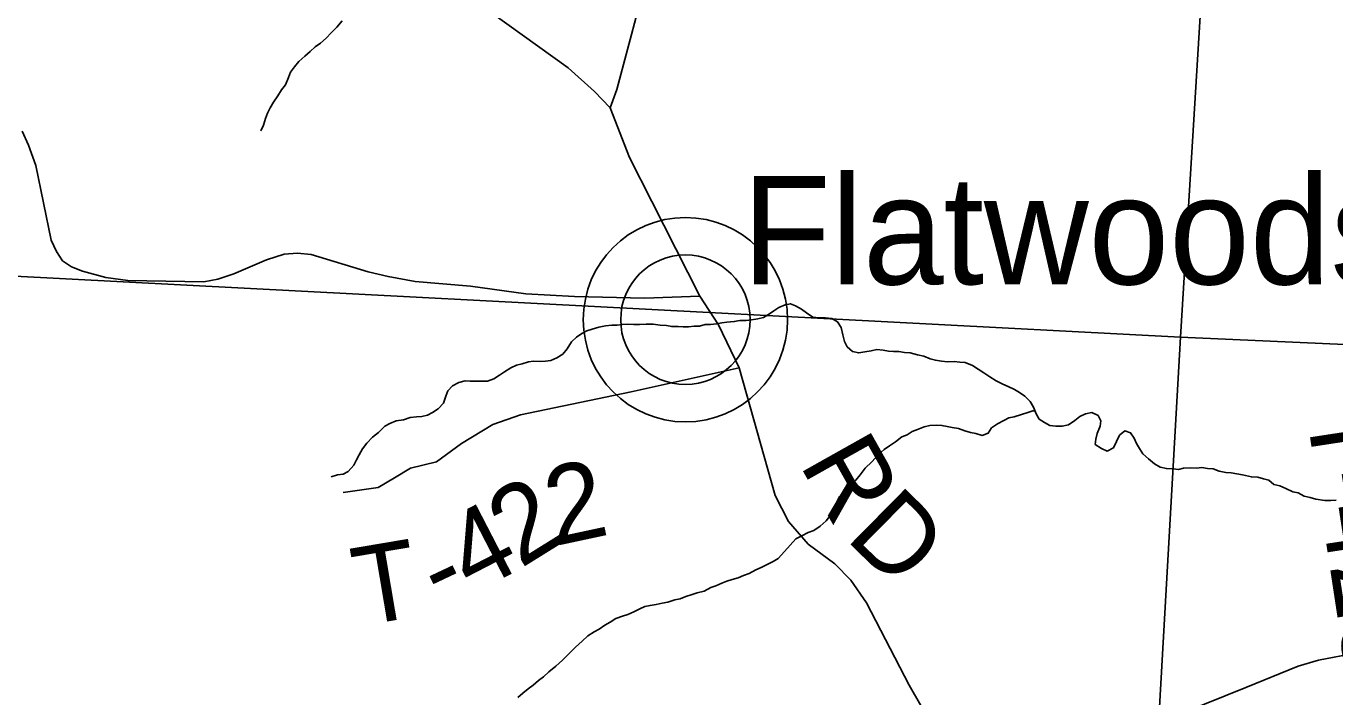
# Model space of a CAD drawing. Extents: x -20.2 to 34, y 0 to 22.
# Drawn here: x 7.079 to 8.033, y 16.636 to 17.124 of the extents above; entities that cross this region are included whole.
import ezdxf

# ---------------------------------------------------------------- set-up
doc = ezdxf.new("R2010")
doc.units = 0
for name, color, linetype in [('Default', 7, 'Continuous'), ('GM_X_County_Road', 7, 'Continuous'), ('GM_X_County_Road_Text', 7, 'Continuous'), ('GM_X_Minor_River', 7, 'Continuous'), ('GM_X_Section', 7, 'Continuous'), ('GM_X_Township_Road', 7, 'Continuous'), ('GM_X_Township_Road_Text', 7, 'Continuous'), ('GM_X_Unincorporated', 7, 'Continuous'), ('GM_X_Unincorporated_Location', 7, 'Continuous'), ('GM_X_Unincorporated_Text', 7, 'Continuous')]:
    doc.layers.add(name, color=color, linetype=linetype)

msp = doc.modelspace()

# ---------------------------------------------------------------- linework, layer by layer
at = {"layer": 'Default'}
for points in [[(8.9, 16.85373), (8.9, 17.84514), (7.98194, 17.90766), (7.92004, 16.89751)], [(8.9, 15.82114), (8.9, 16.85373), (7.92004, 16.89751), (7.86237, 15.87982)]]:
    msp.add_lwpolyline(points, close=True, dxfattribs=at)
at = {"layer": 'GM_X_County_Road'}
for points in [[(7.5047, 17.06445), (7.50945, 17.07768), (7.53298, 17.1663)], [(7.40706, 17.1417), (7.47411, 17.09347), (7.49333, 17.07622), (7.5047, 17.06445), (7.51882, 17.02837), (7.5349, 16.99622), (7.56986, 16.92742), (7.58352, 16.90642), (7.59849, 16.87511), (7.62484, 16.78214), (7.6345, 16.76328), (7.64898, 16.74682), (7.66821, 16.73251), (7.67999, 16.72053), (7.69136, 16.70406), (7.72235, 16.64406), (7.74979, 16.59622)], [(7.90619, 16.61759), (7.96766, 16.64232), (8.00584, 16.65793), (8.02072, 16.66225), (8.04858, 16.66753)]]:
    msp.add_lwpolyline(points, dxfattribs=at)
at = {"layer": 'GM_X_Minor_River'}
for points in [[(7.25027, 17.04764), (7.25212, 17.05185), (7.25358, 17.0568), (7.25506, 17.06062), (7.25691, 17.06444), (7.25952, 17.06865), (7.2625, 17.07325), (7.26511, 17.07746), (7.2681, 17.08129), (7.27032, 17.08664), (7.27179, 17.09046), (7.27478, 17.09429), (7.27777, 17.09813), (7.28228, 17.10199), (7.28604, 17.10545), (7.28979, 17.10892), (7.29356, 17.11163), (7.29769, 17.1151), (7.30144, 17.11894), (7.30557, 17.12317), (7.30931, 17.12778)], [(7.30143, 16.79569), (7.30596, 16.79727), (7.31014, 16.7977), (7.31391, 16.79965), (7.31803, 16.80426), (7.31988, 16.80808), (7.32174, 16.8119), (7.32434, 16.81611), (7.32733, 16.82033), (7.33146, 16.82456), (7.33597, 16.82803), (7.34047, 16.83264), (7.34425, 16.83459), (7.34878, 16.83655), (7.35408, 16.83738), (7.359, 16.83896), (7.36355, 16.83939), (7.36734, 16.83982), (7.37151, 16.84063), (7.37528, 16.84258), (7.37942, 16.84529), (7.38317, 16.84952), (7.38501, 16.85448), (7.38648, 16.85829), (7.38985, 16.86213), (7.39438, 16.86447), (7.39892, 16.86567), (7.40272, 16.86533), (7.40652, 16.86538), (7.41032, 16.86543), (7.41525, 16.86549), (7.41978, 16.86707), (7.42393, 16.86978), (7.4277, 16.87211), (7.43221, 16.8752), (7.43637, 16.87715), (7.44053, 16.87796), (7.44507, 16.87954), (7.44886, 16.87997), (7.4538, 16.87965), (7.45759, 16.88008), (7.46138, 16.8805), (7.46591, 16.88246), (7.47006, 16.88517), (7.47343, 16.88901), (7.47641, 16.89399), (7.48016, 16.89745), (7.48393, 16.90016), (7.4877, 16.90211), (7.49148, 16.90329), (7.4964, 16.90487), (7.50132, 16.9057), (7.50587, 16.90613), (7.50967, 16.90618), (7.51346, 16.90661), (7.51763, 16.90704), (7.52181, 16.90671), (7.52599, 16.90677), (7.53092, 16.90683), (7.53585, 16.90689), (7.54117, 16.9062), (7.54573, 16.90587), (7.54954, 16.90516), (7.55409, 16.90522), (7.55789, 16.90489), (7.56169, 16.90494), (7.56586, 16.90537), (7.56965, 16.90542), (7.57382, 16.90661), (7.57761, 16.90666), (7.58216, 16.90709), (7.58595, 16.9079), (7.58974, 16.90833), (7.59505, 16.90877), (7.59921, 16.90959), (7.60377, 16.90964), (7.60756, 16.91007), (7.6121, 16.91089), (7.61627, 16.9117), (7.62004, 16.91403), (7.6238, 16.91673), (7.62757, 16.91906), (7.6321, 16.92101), (7.63589, 16.92182), (7.6397, 16.92035), (7.64391, 16.91775), (7.64774, 16.91513), (7.65233, 16.91215), (7.65689, 16.91145), (7.66144, 16.91151), (7.666, 16.91118), (7.67021, 16.90858), (7.67291, 16.90443), (7.67411, 16.89913), (7.67531, 16.89421), (7.67725, 16.89044), (7.68109, 16.88707), (7.68566, 16.88598), (7.6902, 16.8868), (7.69475, 16.88762), (7.69891, 16.88843)], [(7.69891, 16.88843), (7.70347, 16.88811), (7.70728, 16.88739), (7.71108, 16.88706), (7.71487, 16.88711), (7.71906, 16.8864), (7.72323, 16.88608), (7.72857, 16.88462), (7.73313, 16.88354), (7.73771, 16.8817), (7.74152, 16.88061), (7.74608, 16.87991), (7.75064, 16.87958), (7.7552, 16.87964), (7.75937, 16.87932), (7.76317, 16.87898), (7.76851, 16.87677), (7.77272, 16.87417), (7.77693, 16.87156), (7.78114, 16.86857), (7.78573, 16.86559), (7.79069, 16.86337), (7.7945, 16.86152), (7.79909, 16.8593), (7.80291, 16.85707), (7.80673, 16.85446), (7.81057, 16.85071), (7.8129, 16.84656), (7.81485, 16.84165), (7.81718, 16.83788), (7.821, 16.83527), (7.82483, 16.83304), (7.82939, 16.83271), (7.83394, 16.83277), (7.83848, 16.83359), (7.843, 16.83668), (7.84676, 16.83977), (7.85092, 16.84172), (7.85546, 16.84254), (7.86004, 16.84032), (7.86198, 16.83654), (7.86165, 16.83274), (7.85943, 16.82739), (7.85834, 16.8232), (7.85801, 16.8194), (7.8626, 16.81642), (7.86679, 16.81457), (7.87132, 16.81691), (7.87355, 16.8215), (7.87577, 16.82608), (7.87953, 16.82917), (7.88372, 16.8277), (7.88642, 16.82394), (7.88799, 16.82016), (7.89031, 16.81639), (7.89263, 16.81262), (7.89685, 16.80887), (7.90107, 16.80513), (7.90527, 16.8029), (7.90984, 16.80182), (7.91478, 16.8015), (7.91857, 16.80117), (7.92236, 16.80198), (7.92729, 16.80242), (7.93185, 16.8021), (7.93564, 16.80252), (7.93982, 16.80182), (7.944, 16.80149), (7.9482, 16.80002), (7.95314, 16.79895), (7.95694, 16.79861), (7.96113, 16.79791), (7.96531, 16.7972), (7.97178, 16.79576), (7.97634, 16.79544), (7.98053, 16.79435), (7.98434, 16.79326), (7.98817, 16.79027), (7.99236, 16.78918), (7.99693, 16.78734), (8.0019, 16.78475), (8.0057, 16.78403), (8.01028, 16.78181), (8.01447, 16.78072), (8.01866, 16.77964), (8.02512, 16.77858), (8.02968, 16.77864), (8.03347, 16.77868)], [(7.60176, 16.72388), (7.60592, 16.72545), (7.61082, 16.72817), (7.6146, 16.72974), (7.61951, 16.73208), (7.62328, 16.73403), (7.62705, 16.73636), (7.63155, 16.74135), (7.63567, 16.74596), (7.63979, 16.75057), (7.64432, 16.7529), (7.64885, 16.75524), (7.653, 16.75681), (7.65752, 16.75991), (7.66203, 16.76376), (7.66577, 16.76875), (7.66761, 16.77333), (7.66947, 16.77715), (7.67169, 16.78136), (7.67544, 16.78558), (7.67995, 16.78982), (7.6837, 16.79328), (7.68669, 16.79712), (7.69043, 16.8021), (7.69531, 16.80672), (7.69981, 16.81171), (7.70432, 16.81557), (7.70808, 16.81828), (7.7126, 16.82137), (7.71712, 16.82485), (7.72089, 16.82641), (7.72466, 16.82874), (7.72844, 16.83031), (7.73335, 16.83227), (7.73752, 16.83308), (7.74245, 16.83352), (7.74625, 16.83319), (7.75005, 16.83248), (7.75386, 16.83176), (7.75842, 16.83106), (7.763, 16.82922), (7.76718, 16.82814), (7.77099, 16.82742), (7.77556, 16.82596), (7.7801, 16.82754), (7.78233, 16.83136), (7.78685, 16.83446), (7.79138, 16.83679), (7.79515, 16.83874), (7.79894, 16.83955), (7.80423, 16.84114), (7.80877, 16.84271), (7.81255, 16.8439), (7.8141, 16.84355)], [(7.43729, 16.63522), (7.44106, 16.63831), (7.44482, 16.64139), (7.44858, 16.6441), (7.45234, 16.64756), (7.4561, 16.65027), (7.45985, 16.65373), (7.46512, 16.65798), (7.47, 16.66222), (7.47413, 16.66645), (7.47938, 16.67183), (7.48427, 16.67607), (7.4884, 16.67992), (7.49292, 16.68301), (7.49669, 16.68496), (7.50083, 16.68767), (7.5046, 16.69), (7.50875, 16.69271), (7.51366, 16.69429), (7.51744, 16.69548), (7.52198, 16.69743), (7.52613, 16.69976), (7.5299, 16.70133), (7.53369, 16.70214), (7.53824, 16.70295), (7.5424, 16.70377), (7.54657, 16.70458), (7.55186, 16.70616), (7.55565, 16.70697), (7.55981, 16.70854), (7.56434, 16.71012), (7.56813, 16.71131), (7.57305, 16.71251), (7.57795, 16.71523), (7.58173, 16.71641), (7.58588, 16.71836), (7.58966, 16.71993), (7.59344, 16.72112), (7.59798, 16.72232), (7.60176, 16.72388)]]:
    msp.add_lwpolyline(points, dxfattribs=at)
at = {"layer": 'GM_X_Section'}
for points in [[(6.91499, 17.96388), (7.98194, 17.90766), (7.92004, 16.89751), (6.85272, 16.95336)], [(6.85272, 16.95336), (7.92004, 16.89751), (7.86237, 15.87982), (6.79044, 15.94473), (6.80008, 16.11433), (6.82053, 16.44033)]]:
    msp.add_lwpolyline(points, close=True, dxfattribs=at)
at = {"layer": 'GM_X_Township_Road'}
for points in [[(7.07621, 17.04742), (7.08097, 17.03726), (7.08628, 17.0224), (7.09753, 16.96816), (7.10122, 16.95993), (7.10576, 16.95305), (7.11231, 16.94868), (7.12037, 16.94549), (7.13733, 16.94096), (7.15328, 16.93878), (7.2087, 16.93777), (7.21877, 16.93962), (7.23052, 16.94349), (7.25437, 16.95389), (7.26713, 16.95792), (7.27687, 16.95859), (7.28678, 16.95759), (7.32825, 16.94516), (7.34286, 16.94163), (7.36268, 16.93811), (7.40281, 16.93458), (7.44311, 16.92903), (7.47854, 16.92702), (7.52976, 16.92585), (7.56986, 16.92742)], [(7.31019, 16.78445), (7.33568, 16.78798), (7.34745, 16.79504), (7.35921, 16.8021), (7.37803, 16.8068), (7.39641, 16.82013), (7.41921, 16.83399), (7.43921, 16.84092), (7.52, 16.85779), (7.59849, 16.87511)]]:
    msp.add_lwpolyline(points, dxfattribs=at)
at = {"layer": 'GM_X_Unincorporated'}
for radius in [0.0744, 0.04716]:
    msp.add_circle((7.55946, 16.9102), radius, dxfattribs=at)
at = {"layer": 'GM_X_Unincorporated_Location'}
msp.add_line((7.55946, 16.9102), (7.55946, 16.9102), dxfattribs=at)

# ---------------------------------------------------------------- texts
at = {"layer": 'GM_X_County_Road_Text'}
for s, rotation, p in [('R', 299.30822, (7.64204, 16.80531)), ('D', 315.38308, (7.67523, 16.75106))]:
    msp.add_text(s, height=0.05682, rotation=rotation, dxfattribs=at).set_placement(p)
at = {"layer": 'GM_X_Township_Road_Text'}
for s, height, rotation, p in [('T-428', 0.056818, 278.67887, (8.01148, 16.84403)), ('2', 0.05682, 12.08967, (7.46421, 16.74526)), ('2', 0.05682, 31.8866, (7.43928, 16.72871)), ('4', 0.05682, 27.33274, (7.40391, 16.71021)), ('T', 0.05682, 9.59337, (7.32277, 16.68713)), ('-', 0.05682, 25.22311, (7.38075, 16.69925))]:
    msp.add_text(s, height=height, rotation=rotation, dxfattribs=at).set_placement(p)
at = {"layer": 'GM_X_Unincorporated_Text'}
msp.add_text('Flatwoods', height=0.078977, rotation=0.00001, dxfattribs=at).set_placement((7.60083, 16.93589))

doc.saveas('drawing.dxf')
